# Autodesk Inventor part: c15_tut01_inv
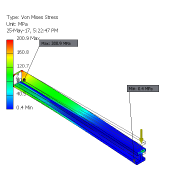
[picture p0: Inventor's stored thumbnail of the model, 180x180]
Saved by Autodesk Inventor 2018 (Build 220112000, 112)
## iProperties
Created: 2017-05
Part Number: c15_tut01_inv
Material: Steel, Alloy
Document SubType Name: Modeling
Designer: CADCIM 00
Mass: 637.725 g
Surface Area: 365.5 cm^2
Volume: 82.5 cm^3
Density: 7.73 g/cm^3
Appearance: Semi-Polished
Author: CADCIM 00
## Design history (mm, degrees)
sketch "Sketch1"
  geometry: L1 (-10, 25)-(10, 25); L2 (10, 25)-(10, 20); L3 (10, 20)-(2.5, 20); L4 (2.5, 20)-(2.5, 5); L5 (2.5, 5)-(10, 5); L6 (10, 5)-(10, 0); L7 (10, 0)-(-10, 0); L8 (-10, 0)-(-10, 5); L9 (-10, 5)-(-2.5, 5); L10 (-2.5, 5)-(-2.5, 20); L11 (-2.5, 20)-(-10, 20); L12 (-10, 25)-(-10, 20); 2 further points
  constraints: 24 end point, 8 perpendicular, 7 point on line, 2 collinear, 1 coincident, 1 horizontal, 1 midpoint
  dimensions: "d0" = 20 distance of L1.start L1.end; "d1" = 5 distance between parallel lines of L3 L1; "d2" = 15 distance between parallel lines of L5 L3; "d3" = 5 distance between parallel lines of L4 L10
extrude "Extrusion1" new body sketch "Sketch1" distance "d4" = 300; taper "d5" = 0 deg
body "Solid1"
other parameters: "sa_0" = 0, "sa_1" = 0, "sa_2" = -1000000
